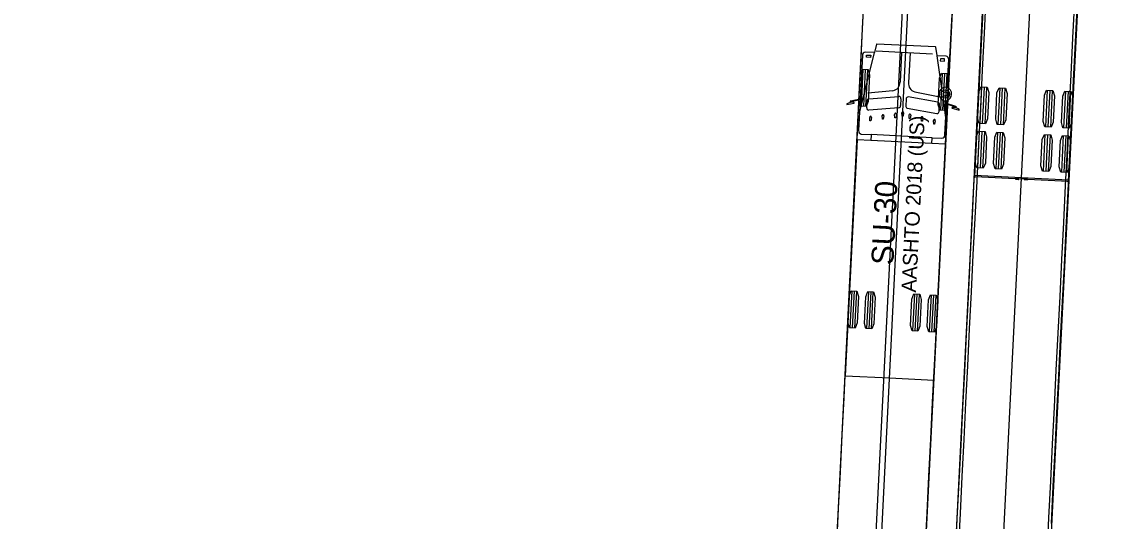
# Model space of a CAD drawing. Extents: x 260275 to 261282, y 610916 to 614143.
# Drawn here: x 260986.2 to 261084.7, y 612452.2 to 612497.2 of the extents above; entities that cross this region are included whole.
import ezdxf

# ---------------------------------------------------------------- set-up
doc = ezdxf.new("R2010")
doc.units = 0
doc.layers.add('GE_X_Alignment', color=7, linetype='Continuous')
doc.layers.add('TopoDOT_Transients', color=7, linetype='Continuous')

msp = doc.modelspace()

# ---------------------------------------------------------------- linework, layer by layer
at = {"layer": 'GE_X_Alignment'}
msp.add_line((260986.249, 610915.954), (261148.276, 614142.838), dxfattribs=at)
at = {"layer": 'TopoDOT_Transients'}
for p, q in [((261059.045, 612136.423), (261081.046, 612574.591)), ((261048.059, 612136.974), (261068.197, 612538.052)), ((261061.83, 612489.013), (261063.171, 612494.481)), ((261068.425, 612494.34), (261063.327, 612494.596)), ((261065.626, 612494.48), (261065.493, 612491.816)), ((261066.391, 612494.442), (261066.257, 612491.777)), ((261062.46, 612494.06), (261062.469, 612494.254)), ((261062.838, 612494.041), (261062.46, 612494.06)), ((261062.469, 612494.254), (261062.848, 612494.235)), ((261062.848, 612494.235), (261062.838, 612494.041)), ((261069.253, 612491.231), (261068.834, 612494.196)), ((261069.131, 612493.92), (261069.122, 612493.726)), ((261069.122, 612493.726), (261069.5, 612493.707)), ((261069.51, 612493.901), (261069.131, 612493.92)), ((261069.5, 612493.707), (261069.51, 612493.901)), ((261069.756, 612491.321), (261069.883, 612493.84)), ((261062.138, 612492.975), (261061.971, 612489.646)), ((261062.346, 612492.965), (261062.179, 612489.636)), ((261062.554, 612492.955), (261062.387, 612489.625)), ((261069.295, 612492.616), (261069.128, 612489.287)), ((261069.503, 612492.606), (261069.336, 612489.276)), ((261069.711, 612492.595), (261069.544, 612489.266)), ((261072.842, 612491.377), (261072.676, 612488.081)), ((261073.071, 612491.366), (261072.905, 612488.07)), ((261073.3, 612491.354), (261073.134, 612488.058)), ((261064.854, 612491.04), (261062.576, 612490.809)), ((261062.683, 612490.31), (261065.391, 612490.526)), ((261068.902, 612489.997), (261066.229, 612490.484)), ((261066.815, 612490.941), (261069.07, 612490.481)), ((261074.49, 612491.295), (261074.324, 612487.999)), ((261074.719, 612491.283), (261074.553, 612487.987)), ((261074.948, 612491.272), (261074.782, 612487.976)), ((261078.768, 612491.08), (261078.602, 612487.784)), ((261078.997, 612491.068), (261078.831, 612487.772)), ((261079.225, 612491.057), (261079.06, 612487.761)), ((261080.416, 612490.997), (261080.25, 612487.701)), ((261080.645, 612490.986), (261080.479, 612487.69)), ((261080.873, 612490.974), (261080.708, 612487.678)), ((261062.49, 612489.5), (261062.521, 612490.115)), ((261065.37, 612489.505), (261062.661, 612489.289)), ((261065.562, 612490.315), (261065.532, 612489.699)), ((261066.037, 612490.291), (261066.006, 612489.675)), ((261066.148, 612489.466), (261068.821, 612488.979)), ((261069.013, 612489.172), (261069.044, 612489.788)), ((261069.62, 612488.622), (261069.404, 612490.156)), ((261062.773, 612488.329), (261062.752, 612488.63)), ((261062.907, 612488.623), (261062.856, 612488.325)), ((261063.9, 612488.483), (261063.879, 612488.798)), ((261063.982, 612488.479), (261063.9, 612488.483)), ((261064.033, 612488.79), (261063.982, 612488.479)), ((261065.025, 612488.609), (261065.004, 612488.911)), ((261065.107, 612488.605), (261065.025, 612488.609)), ((261065.158, 612488.903), (261065.107, 612488.605)), ((261065.68, 612488.745), (261065.66, 612489.046)), ((261065.763, 612488.741), (261065.68, 612488.745)), ((261065.814, 612489.038), (261065.763, 612488.741)), ((261066.319, 612488.544), (261066.299, 612488.846)), ((261066.402, 612488.54), (261066.319, 612488.544)), ((261066.453, 612488.838), (261066.402, 612488.54)), ((261067.426, 612488.306), (261067.405, 612488.607)), ((261067.559, 612488.6), (261067.508, 612488.302)), ((261062.856, 612488.325), (261062.773, 612488.329)), ((261067.508, 612488.302), (261067.426, 612488.306)), ((261068.531, 612488.04), (261068.51, 612488.341)), ((261068.614, 612488.036), (261068.531, 612488.04)), ((261068.665, 612488.334), (261068.614, 612488.036)), ((261068.347, 612486.276), (261062.862, 612486.551)), ((261068.374, 612486.806), (261062.889, 612487.082)), ((261072.641, 612487.382), (261072.476, 612484.087)), ((261072.87, 612487.371), (261072.705, 612484.075)), ((261073.099, 612487.359), (261072.934, 612484.064)), ((261074.289, 612487.3), (261074.124, 612484.004)), ((261074.518, 612487.288), (261074.353, 612483.992)), ((261074.747, 612487.277), (261074.581, 612483.981)), ((261078.567, 612487.085), (261078.402, 612483.789)), ((261078.796, 612487.073), (261078.631, 612483.777)), ((261079.025, 612487.062), (261078.859, 612483.766)), ((261080.215, 612487.002), (261080.05, 612483.706)), ((261080.444, 612486.991), (261080.278, 612483.695)), ((261080.673, 612486.979), (261080.507, 612483.683)), ((261080.701, 612482.964), (261072.211, 612483.39)), ((261076.187, 612483.12), (261075.922, 612483.133)), ((261076.193, 612483.119), (261076.716, 612483.093)), ((261076.452, 612483.106), (261076.456, 612483.177)), ((261076.983, 612483.08), (261076.718, 612483.093)), ((261061.135, 612473.001), (261060.968, 612469.671)), ((261061.343, 612472.99), (261061.176, 612469.661)), ((261061.551, 612472.98), (261061.384, 612469.651)), ((261062.633, 612472.925), (261062.466, 612469.596)), ((261062.841, 612472.915), (261062.674, 612469.586)), ((261063.049, 612472.905), (261062.882, 612469.575)), ((261066.794, 612472.716), (261066.627, 612469.387)), ((261067.002, 612472.706), (261066.835, 612469.377)), ((261067.21, 612472.696), (261067.043, 612469.366)), ((261068.292, 612472.641), (261068.125, 612469.312)), ((261068.5, 612472.631), (261068.333, 612469.302)), ((261068.709, 612472.62), (261068.541, 612469.291))]:
    msp.add_line(p, q, dxfattribs=at)
for points in [[(261080.675, 612482.894), (261080.697, 612482.893), (261083.101, 612530.762), (261078.856, 612530.976), (261074.611, 612531.189), (261072.208, 612483.32), (261072.23, 612483.318)], [(261051.548, 612071.863), (261074.206, 612523.277)], [(261082.631, 612521.243), (261060.03, 612071.291)], [(261042.767, 612111.356), (261063.016, 612514.614)], [(261070.923, 612512.551), (261050.75, 612110.806)], [(261059.773, 612450.044), (261059.941, 612453.373), (261060.108, 612456.701), (261060.275, 612460.03), (261060.442, 612463.358), (261060.609, 612466.687), (261060.776, 612470.015), (261060.943, 612473.344), (261061.11, 612476.672), (261061.278, 612480), (261061.445, 612483.329), (261061.612, 612486.657), (261061.779, 612489.986), (261061.946, 612493.314), (261062.113, 612496.643), (261062.28, 612499.971)], [(261059.774, 612450.049), (261059.941, 612453.377), (261060.108, 612456.706), (261060.275, 612460.034), (261060.442, 612463.362), (261060.609, 612466.691), (261060.776, 612470.019), (261060.944, 612473.348), (261061.111, 612476.676), (261061.278, 612480.005), (261061.445, 612483.333), (261061.612, 612486.662), (261061.779, 612489.99), (261061.946, 612493.318), (261062.113, 612496.647), (261062.281, 612499.975)], [(261067.763, 612449.643), (261067.931, 612452.972), (261068.098, 612456.3), (261068.265, 612459.629), (261068.432, 612462.957), (261068.599, 612466.285), (261068.766, 612469.614), (261068.933, 612472.942), (261069.1, 612476.271), (261069.268, 612479.599), (261069.435, 612482.928), (261069.602, 612486.256), (261069.769, 612489.585), (261069.936, 612492.913), (261070.103, 612496.242), (261070.27, 612499.57)], [(261067.764, 612449.647), (261067.931, 612452.976), (261068.098, 612456.304), (261068.265, 612459.633), (261068.432, 612462.961), (261068.599, 612466.29), (261068.766, 612469.618), (261068.933, 612472.947), (261069.101, 612476.275), (261069.268, 612479.603), (261069.435, 612482.932), (261069.602, 612486.26), (261069.769, 612489.589), (261069.936, 612492.917), (261070.103, 612496.246), (261070.271, 612499.574)], [(261070.765, 612449.6), (261070.932, 612452.93), (261071.099, 612456.259), (261071.267, 612459.589), (261071.434, 612462.918), (261071.601, 612466.248), (261071.768, 612469.578), (261071.935, 612472.907), (261072.102, 612476.237), (261072.27, 612479.566), (261072.437, 612482.896), (261072.604, 612486.225), (261072.771, 612489.555), (261072.938, 612492.884), (261073.106, 612496.214), (261073.273, 612499.543)], [(261070.491, 612449.121), (261070.658, 612452.45), (261070.825, 612455.78), (261070.992, 612459.109), (261071.159, 612462.439), (261071.327, 612465.768), (261071.494, 612469.098), (261071.661, 612472.428), (261071.828, 612475.757), (261071.995, 612479.087), (261072.162, 612482.416), (261072.33, 612485.746), (261072.497, 612489.075), (261072.664, 612492.405), (261072.831, 612495.734), (261072.998, 612499.064)], [(261078.755, 612449.199), (261078.922, 612452.529), (261079.089, 612455.858), (261079.256, 612459.188), (261079.424, 612462.517), (261079.591, 612465.847), (261079.758, 612469.176), (261079.925, 612472.506), (261080.092, 612475.835), (261080.26, 612479.165), (261080.427, 612482.495), (261080.594, 612485.824), (261080.761, 612489.154), (261080.928, 612492.483), (261081.095, 612495.813), (261081.263, 612499.142)], [(261079.147, 612452.024), (261079.314, 612455.354), (261079.481, 612458.683), (261079.649, 612462.013), (261079.816, 612465.342), (261079.983, 612468.672), (261080.15, 612472.001), (261080.317, 612475.331), (261080.485, 612478.66), (261080.652, 612481.99), (261080.819, 612485.319), (261080.986, 612488.649), (261081.153, 612491.979), (261081.32, 612495.308), (261081.488, 612498.638)], [(261069.645, 612494.156), (261068.838, 612494.196), (261068.834, 612494.201), (261068.724, 612494.979), (261068.682, 612494.983), (261066.042, 612495.116), (261063.401, 612495.248), (261063.359, 612495.248), (261063.172, 612494.485), (261063.167, 612494.481), (261062.361, 612494.521)], [(261062.092, 612494.231), (261061.895, 612490.303), (261061.888, 612490.292), (261061.046, 612490.107), (261061.045, 612490.107)], [(261061.001, 612490.037), (261060.998, 612489.99), (261060.998, 612489.989), (261060.696, 612489.872), (261060.693, 612489.807), (261060.696, 612489.808), (261061.358, 612489.914), (261061.361, 612489.915), (261061.364, 612489.97), (261061.362, 612489.971), (261061.045, 612489.995), (261061.044, 612489.996), (261061.047, 612490.04)], [(261061.059, 612490.059), (261061.06, 612490.059), (261061.887, 612490.238), (261061.891, 612490.225), (261061.752, 612487.455)], [(261069.542, 612487.064), (261069.681, 612489.834), (261069.687, 612489.846), (261070.492, 612489.586), (261070.492, 612489.586)], [(261070.511, 612489.632), (261070.51, 612489.632), (261069.691, 612489.9), (261069.685, 612489.912), (261069.697, 612490.14)], [(261070.502, 612489.565), (261070.501, 612489.521), (261070.5, 612489.52), (261070.183, 612489.528), (261070.18, 612489.528), (261070.177, 612489.472), (261070.18, 612489.471), (261070.829, 612489.299), (261070.831, 612489.298), (261070.835, 612489.363), (261070.547, 612489.51), (261070.547, 612489.51), (261070.548, 612489.557)], [(261061.991, 612487.127), (261062.886, 612487.082), (261062.889, 612487.078), (261062.862, 612486.552), (261062.851, 612486.551), (261061.61, 612486.614), (261060.542, 612465.354), (261064.537, 612465.153), (261068.532, 612464.953), (261069.6, 612486.213), (261068.358, 612486.275), (261068.347, 612486.276), (261068.374, 612486.803), (261068.377, 612486.806), (261069.272, 612486.761)], [(261072.254, 612483.317), (261072.255, 612483.317), (261075.886, 612483.135), (261075.922, 612483.133), (261075.918, 612483.063), (261075.92, 612483.063), (261076.186, 612483.049)], [(261076.712, 612483.023), (261076.978, 612483.009), (261076.98, 612483.01), (261076.983, 612483.08), (261077.019, 612483.078), (261080.65, 612482.896), (261080.651, 612482.896)]]:
    msp.add_lwpolyline(points, dxfattribs=at)
for points in [[(261062.086, 612492.978), (261062.605, 612492.952), (261062.739, 612492.478), (261062.618, 612490.081), (261062.438, 612489.623), (261061.919, 612489.649), (261061.786, 612490.123), (261061.906, 612492.52)], [(261069.244, 612492.619), (261069.763, 612492.593), (261069.896, 612492.119), (261069.776, 612489.722), (261069.596, 612489.263), (261069.077, 612489.29), (261068.944, 612489.763), (261069.064, 612492.16)], [(261072.785, 612491.38), (261073.356, 612491.351), (261073.505, 612490.881), (261073.386, 612488.508), (261073.191, 612488.056), (261072.62, 612488.084), (261072.471, 612488.554), (261072.59, 612490.927)], [(261074.433, 612491.297), (261075.004, 612491.269), (261075.153, 612490.799), (261075.034, 612488.426), (261074.839, 612487.973), (261074.268, 612488.002), (261074.119, 612488.472), (261074.238, 612490.845)], [(261078.711, 612491.083), (261079.282, 612491.054), (261079.431, 612490.584), (261079.312, 612488.211), (261079.117, 612487.758), (261078.545, 612487.787), (261078.397, 612488.257), (261078.516, 612490.63)], [(261080.359, 612491), (261080.93, 612490.971), (261081.079, 612490.501), (261080.96, 612488.128), (261080.765, 612487.675), (261080.193, 612487.704), (261080.044, 612488.174), (261080.164, 612490.547)], [(261072.584, 612487.385), (261073.156, 612487.357), (261073.305, 612486.886), (261073.186, 612484.513), (261072.99, 612484.061), (261072.419, 612484.089), (261072.27, 612484.559), (261072.389, 612486.932)], [(261074.232, 612487.302), (261074.804, 612487.274), (261074.953, 612486.804), (261074.833, 612484.431), (261074.638, 612483.978), (261074.067, 612484.007), (261073.918, 612484.477), (261074.037, 612486.85)], [(261078.51, 612487.088), (261079.082, 612487.059), (261079.231, 612486.589), (261079.111, 612484.216), (261078.916, 612483.763), (261078.345, 612483.792), (261078.196, 612484.262), (261078.315, 612486.635)], [(261080.158, 612487.005), (261080.73, 612486.976), (261080.879, 612486.506), (261080.759, 612484.133), (261080.564, 612483.68), (261079.993, 612483.709), (261079.844, 612484.179), (261079.963, 612486.552)], [(261061.083, 612473.003), (261061.602, 612472.977), (261061.736, 612472.503), (261061.615, 612470.106), (261061.435, 612469.648), (261060.916, 612469.674), (261060.783, 612470.148), (261060.903, 612472.545)], [(261062.581, 612472.928), (261063.101, 612472.902), (261063.234, 612472.428), (261063.113, 612470.031), (261062.933, 612469.573), (261062.414, 612469.599), (261062.281, 612470.073), (261062.401, 612472.47)], [(261066.743, 612472.719), (261067.262, 612472.693), (261067.395, 612472.219), (261067.275, 612469.822), (261067.095, 612469.364), (261066.575, 612469.39), (261066.442, 612469.864), (261066.563, 612472.261)], [(261068.241, 612472.644), (261068.76, 612472.618), (261068.893, 612472.144), (261068.773, 612469.747), (261068.593, 612469.289), (261068.074, 612469.315), (261067.941, 612469.789), (261068.061, 612472.186)]]:
    msp.add_lwpolyline(points, close=True, dxfattribs=at)
for centre, radius in [((261069.581, 612490.738), 0.374), ((261069.581, 612490.738), 0.193), ((261072.24, 612483.284), 0.0266), ((261080.661, 612482.861), 0.0266)]:
    msp.add_circle(centre, radius, dxfattribs=at)
for centre, radius, start, end in [((261062.374, 612494.24), 0.282, 92.67391, 181.75333), ((261069.603, 612493.877), 0.282, 352.49767, 81.5771), ((261064.72, 612491.801), 0.773, 280.01597, 1.10013), ((261067.025, 612491.685), 0.773, 173.15088, 254.23504), ((261069.586, 612490.824), 0.526, 71.07067, 129.31667), ((261065.38, 612490.342), 0.184, 351.66723, 86.52737), ((261066.222, 612490.299), 0.184, 87.72364, 182.58377), ((261069.65, 612490.727), 0.63, 176.4803, 228.88311), ((261069.65, 612490.743), 0.629, 129.17109, 177.86038), ((261069.514, 612490.741), 0.628, 286.8788, 67.3705), ((261061.024, 612490.071), 0.0418, 59.61742, 236.63235), ((261061.018, 612490.072), 0.0434, 312.53921, 343.21198), ((261062.673, 612489.473), 0.184, 171.66167, 266.53293), ((261062.714, 612490.119), 0.193, 99.26792, 181.18241), ((261065.339, 612489.695), 0.193, 279.26299, 1.18734), ((261066.198, 612489.652), 0.193, 173.06366, 254.98801), ((261068.852, 612489.811), 0.193, 353.06859, 74.98308), ((261069.577, 612490.651), 0.524, 229.38452, 283.18459), ((261070.535, 612489.594), 0.0434, 191.03902, 221.7118), ((261070.529, 612489.594), 0.0418, 297.61865, 114.63358), ((261062.842, 612488.644), 0.091, 94.64508, 188.80895), ((261062.819, 612488.646), 0.0909, 345.40639, 79.64159), ((261063.969, 612488.798), 0.091, 94.64508, 188.80895), ((261063.945, 612488.8), 0.0909, 345.40639, 79.64159), ((261065.094, 612488.925), 0.091, 94.64508, 188.80895), ((261065.07, 612488.926), 0.0909, 345.40639, 79.64159), ((261065.749, 612489.06), 0.091, 94.64508, 188.80895), ((261065.726, 612489.061), 0.091, 345.44206, 79.60593), ((261066.388, 612488.86), 0.0909, 94.60942, 188.84462), ((261066.365, 612488.861), 0.091, 345.44206, 79.60593), ((261067.495, 612488.621), 0.0909, 94.60942, 188.84462), ((261067.471, 612488.623), 0.091, 345.44206, 79.60593), ((261068.6, 612488.355), 0.0909, 94.60942, 188.84462), ((261068.577, 612488.356), 0.091, 345.44206, 79.60593), ((261068.828, 612489.164), 0.184, 267.71808, 2.58934), ((261062.074, 612487.439), 0.323, 177.1255, 254.97391), ((261069.22, 612487.08), 0.323, 279.2771, 357.1255), ((261072.24, 612483.284), 0.0363, 106.20231, 67.36494), ((261076.187, 612483.084), 0.0352, 86.91304, 269.55244), ((261076.188, 612483.084), 0.0352, 267.14108, 87.72757), ((261076.714, 612483.058), 0.0352, 86.52344, 267.10992), ((261076.714, 612483.058), 0.0354, 271.41704, 83.6025), ((261080.661, 612482.861), 0.0363, 106.88607, 68.0487)]:
    msp.add_arc(centre, radius, start, end, dxfattribs=at)

# ---------------------------------------------------------------- texts
for s, height, p in [('AASHTO 2018 (US)', 1.33333, (261066.932, 612472.829)), ('SU-30', 2, (261064.886, 612475.292))]:
    msp.add_text(s, height=height, rotation=87.1255, dxfattribs=at).set_placement(p)

doc.saveas('drawing.dxf')
